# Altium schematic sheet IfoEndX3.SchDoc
size C; Engineer: Daniel Sigg; DocumentNumber: 7; SheetNumber: 26; SheetTotal: 33
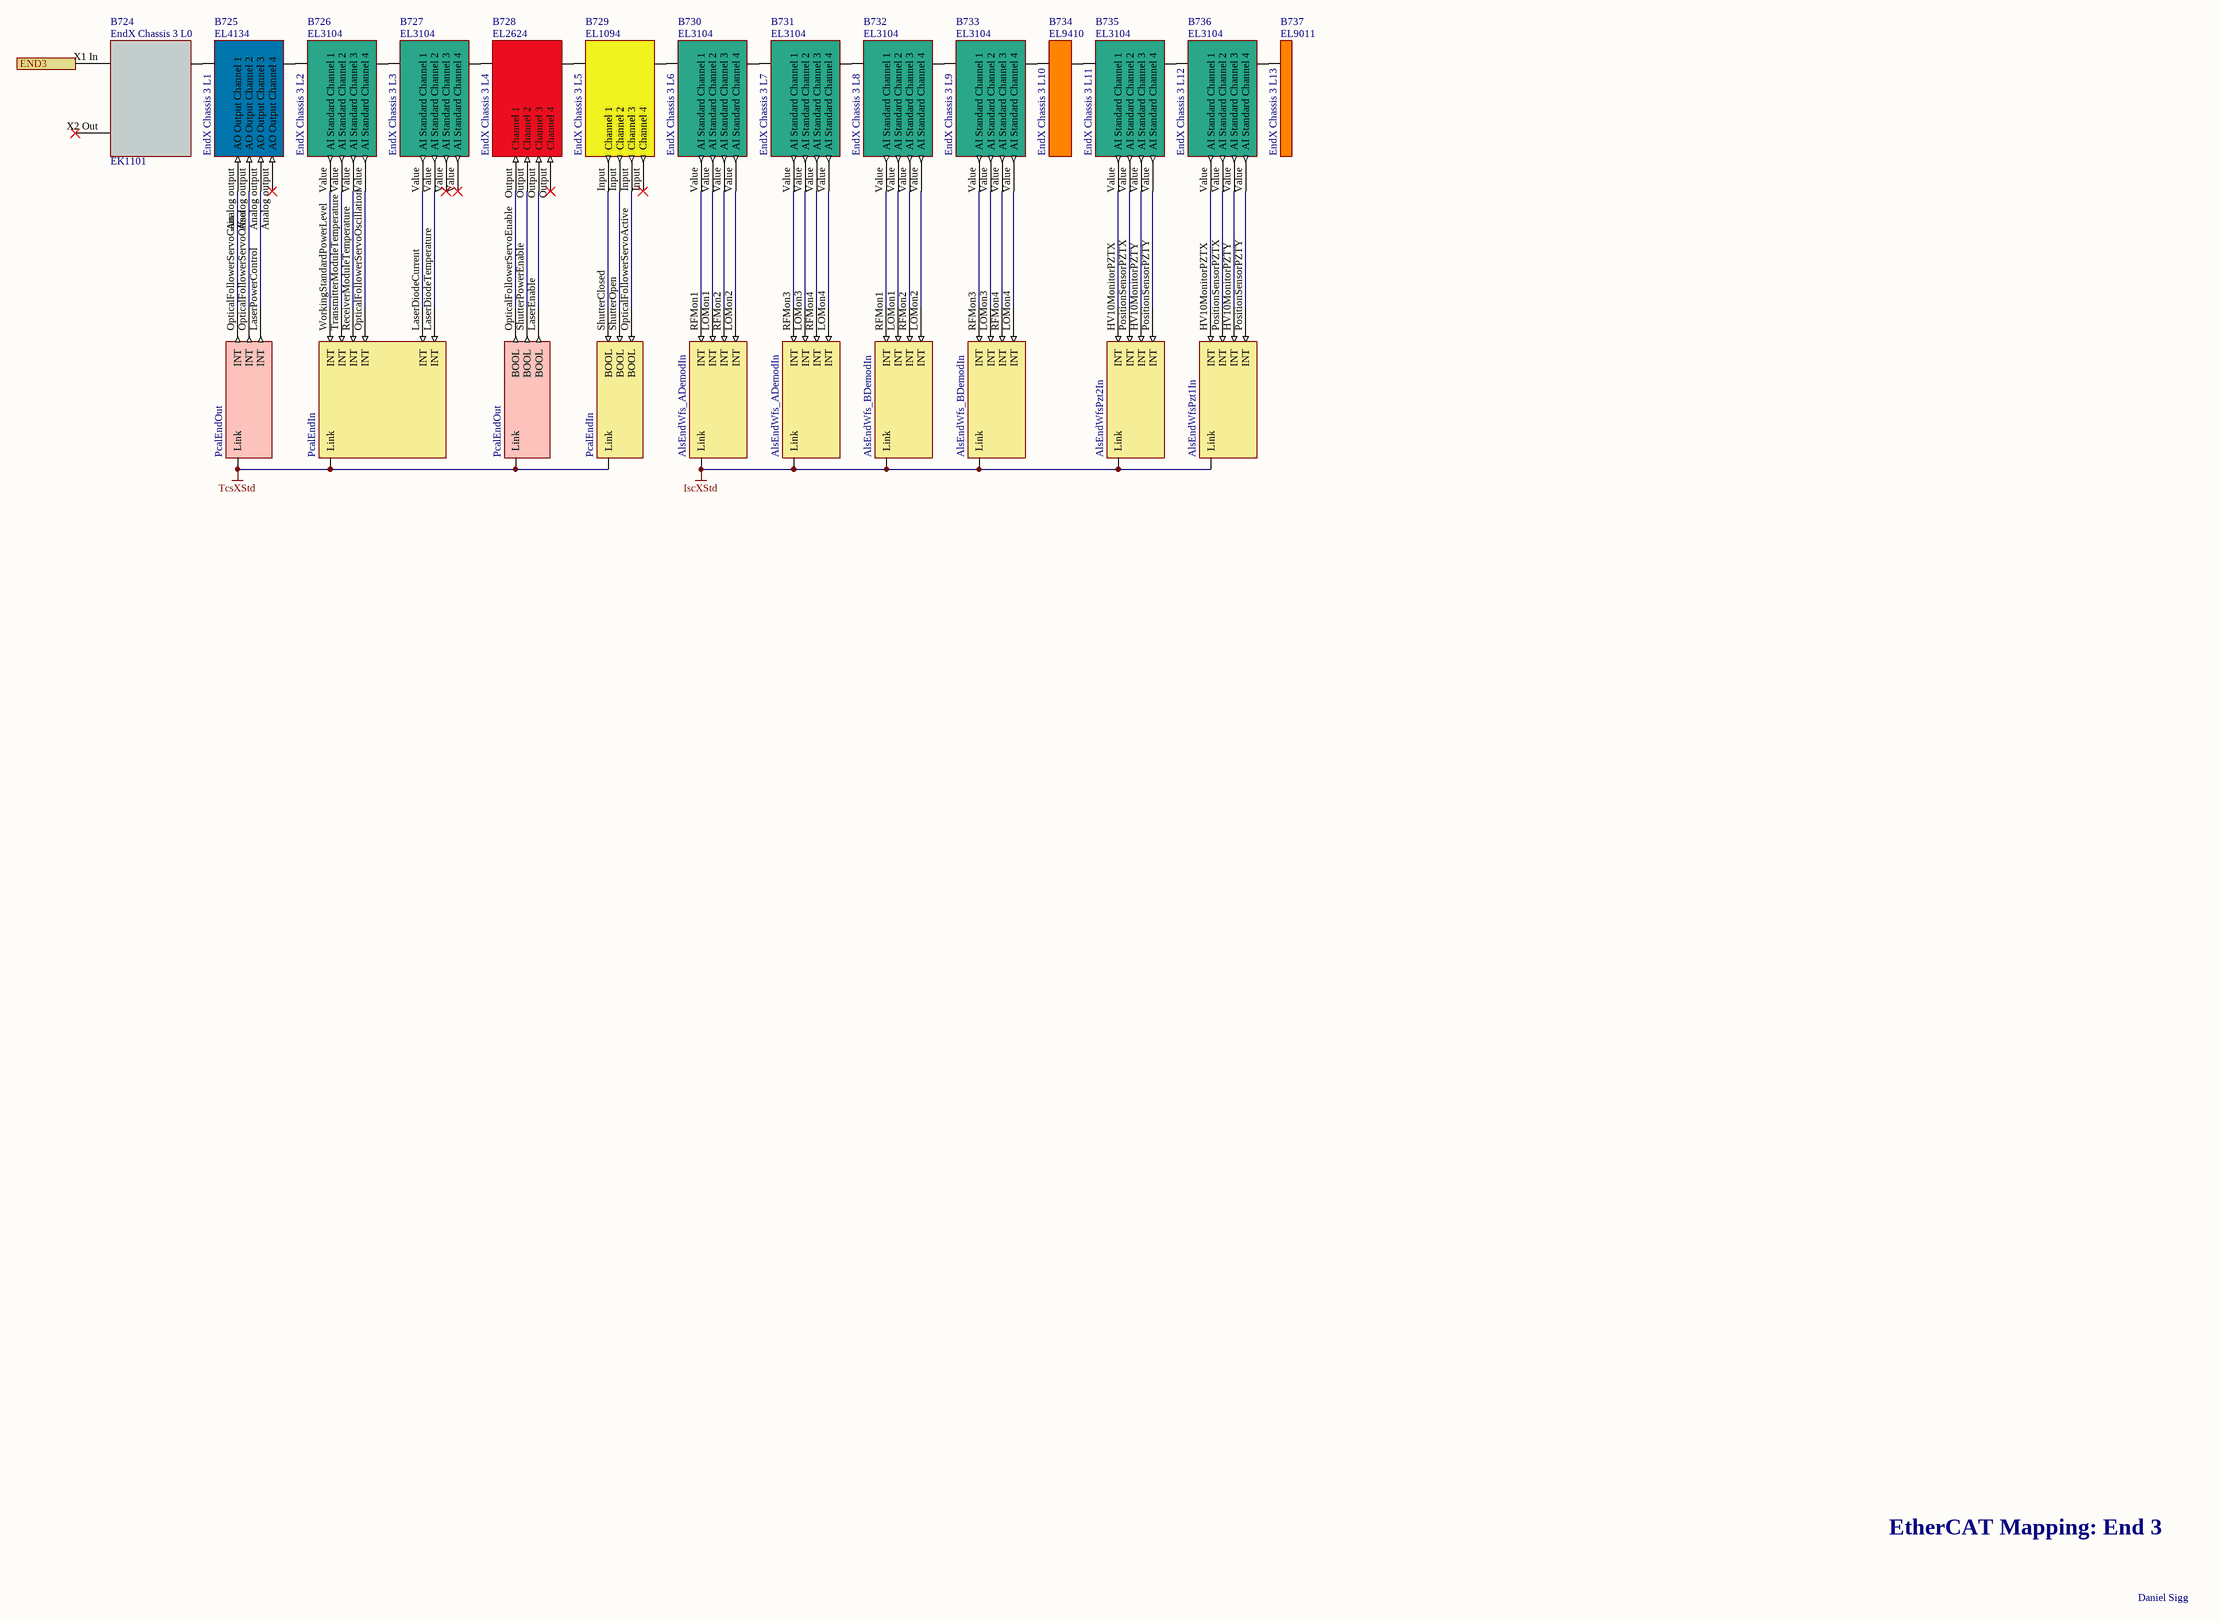
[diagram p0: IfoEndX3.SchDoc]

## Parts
B724  EndX Chassis 3 L0  Part Number: EK1101
B725  EndX Chassis 3 L1  Part Number: EL4134  (mechanical)
B726  EndX Chassis 3 L2  Part Number: EL3104  (mechanical)
B727  EndX Chassis 3 L3  Part Number: EL3104  (mechanical)
B728  EndX Chassis 3 L4  Part Number: EL2624  (mechanical)
B729  EndX Chassis 3 L5  Part Number: EL1094  (mechanical)
B730  EndX Chassis 3 L6  Part Number: EL3104  (mechanical)
B731  EndX Chassis 3 L7  Part Number: EL3104  (mechanical)
B732  EndX Chassis 3 L8  Part Number: EL3104  (mechanical)
B733  EndX Chassis 3 L9  Part Number: EL3104  (mechanical)
B734  EndX Chassis 3 L10  Part Number: EL9410  (mechanical)
B735  EndX Chassis 3 L11  Part Number: EL3104  (mechanical)
B736  EndX Chassis 3 L12  Part Number: EL3104  (mechanical)
B737  EndX Chassis 3 L13  Part Number: EL9011  (mechanical)
V584  PcalEndOut  (parts A,B of 2)  (no BOM)
V585  PcalEndIn  (parts A,B of 2)  (no BOM)
V586  AlsEndWfs_ADemodIn  (parts A,B of 2)  (no BOM)
V594  AlsEndWfs_BDemodIn  (parts A,B of 2)  (no BOM)
V595  AlsEndWfsPzt2In  (no BOM)
V596  AlsEndWfsPzt1In  (no BOM)

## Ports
END3

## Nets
IscXStd: V586.0(Link) V586.1(Link) V594.0(Link) V594.1(Link) V595.0(Link) V596.0(Link)
TcsXStd: V584.0(Link) V584.1(Link) V585.0(Link) V585.1(Link)
END3: B724.X1_In(A) ; port END3
NetB724_Ebus: B724.Ebus(B) B725.Ebus(A)
NetB725_Analog output: B725.Analog_output(AO_Output_Channel_1) V584.OpticalFollowerServoGain(INT)
NetB725_Analog output: B725.Analog_output(AO_Output_Channel_2) V584.OpticalFollowerServoOffset(INT)  [a separate net that carries the same name]
NetB725_Analog output: B725.Analog_output(AO_Output_Channel_3) V584.LaserPowerControl(INT)  [a separate net that carries the same name]
NetB725_Ebus: B725.Ebus(B) B726.Ebus(A)
NetB726_Ebus: B726.Ebus(B) B727.Ebus(A)
NetB726_Value: B726.Value(AI_Standard_Channel_1) V585.WorkingStandardPowerLevel(INT)
NetB726_Value: B726.Value(AI_Standard_Channel_2) V585.TransmitterModuleTemperature(INT)  [a separate net that carries the same name]
NetB726_Value: B726.Value(AI_Standard_Channel_3) V585.ReceiverModuleTemperature(INT)  [a separate net that carries the same name]
NetB726_Value: B726.Value(AI_Standard_Channel_4) V585.OpticalFollowerServoOscillation(INT)  [a separate net that carries the same name]
NetB727_Ebus: B727.Ebus(B) B728.Ebus(A)
NetB727_Value: B727.Value(AI_Standard_Channel_1) V585.LaserDiodeCurrent(INT)
NetB727_Value: B727.Value(AI_Standard_Channel_2) V585.LaserDiodeTemperature(INT)  [a separate net that carries the same name]
NetB728_Ebus: B728.Ebus(B) B729.Ebus(A)
NetB728_Output: B728.Output(Channel_1) V584.OpticalFollowerServoEnable(BOOL)
NetB728_Output: B728.Output(Channel_2) V584.ShutterPowerEnable(BOOL)  [a separate net that carries the same name]
NetB728_Output: B728.Output(Channel_3) V584.LaserEnable(BOOL)  [a separate net that carries the same name]
NetB729_Ebus: B729.Ebus(B) B730.Ebus(A)
NetB729_Input: B729.Input(Channel_1) V585.ShutterClosed(BOOL)
NetB729_Input: B729.Input(Channel_2) V585.ShutterOpen(BOOL)  [a separate net that carries the same name]
NetB729_Input: B729.Input(Channel_3) V585.OpticalFollowerServoActive(BOOL)  [a separate net that carries the same name]
NetB730_Ebus: B730.Ebus(B) B731.Ebus(A)
NetB730_Value: B730.Value(AI_Standard_Channel_1) V586.RFMon1(INT)
NetB730_Value: B730.Value(AI_Standard_Channel_2) V586.LOMon1(INT)  [a separate net that carries the same name]
NetB730_Value: B730.Value(AI_Standard_Channel_3) V586.RFMon2(INT)  [a separate net that carries the same name]
NetB730_Value: B730.Value(AI_Standard_Channel_4) V586.LOMon2(INT)  [a separate net that carries the same name]
NetB731_Ebus: B731.Ebus(B) B732.Ebus(A)
NetB731_Value: B731.Value(AI_Standard_Channel_1) V586.RFMon3(INT)
NetB731_Value: B731.Value(AI_Standard_Channel_2) V586.LOMon3(INT)  [a separate net that carries the same name]
NetB731_Value: B731.Value(AI_Standard_Channel_3) V586.RFMon4(INT)  [a separate net that carries the same name]
NetB731_Value: B731.Value(AI_Standard_Channel_4) V586.LOMon4(INT)  [a separate net that carries the same name]
NetB732_Ebus: B732.Ebus(B) B733.Ebus(A)
NetB732_Value: B732.Value(AI_Standard_Channel_1) V594.RFMon1(INT)
NetB732_Value: B732.Value(AI_Standard_Channel_2) V594.LOMon1(INT)  [a separate net that carries the same name]
NetB732_Value: B732.Value(AI_Standard_Channel_3) V594.RFMon2(INT)  [a separate net that carries the same name]
NetB732_Value: B732.Value(AI_Standard_Channel_4) V594.LOMon2(INT)  [a separate net that carries the same name]
NetB733_Ebus: B733.Ebus(B) B734.Ebus(A)
NetB733_Value: B733.Value(AI_Standard_Channel_1) V594.RFMon3(INT)
NetB733_Value: B733.Value(AI_Standard_Channel_2) V594.LOMon3(INT)  [a separate net that carries the same name]
NetB733_Value: B733.Value(AI_Standard_Channel_3) V594.RFMon4(INT)  [a separate net that carries the same name]
NetB733_Value: B733.Value(AI_Standard_Channel_4) V594.LOMon4(INT)  [a separate net that carries the same name]
NetB734_Ebus: B734.Ebus(B) B735.Ebus(A)
NetB735_Ebus: B735.Ebus(B) B736.Ebus(A)
NetB735_Value: B735.Value(AI_Standard_Channel_1) V595.HV10MonitorPZTX(INT)
NetB735_Value: B735.Value(AI_Standard_Channel_2) V595.PositionSensorPZTX(INT)  [a separate net that carries the same name]
NetB735_Value: B735.Value(AI_Standard_Channel_3) V595.HV10MonitorPZTY(INT)  [a separate net that carries the same name]
NetB735_Value: B735.Value(AI_Standard_Channel_4) V595.PositionSensorPZTY(INT)  [a separate net that carries the same name]
NetB736_Ebus: B736.Ebus(B) B737.Ebus(A)
NetB736_Value: B736.Value(AI_Standard_Channel_1) V596.HV10MonitorPZTX(INT)
NetB736_Value: B736.Value(AI_Standard_Channel_2) V596.PositionSensorPZTX(INT)  [a separate net that carries the same name]
NetB736_Value: B736.Value(AI_Standard_Channel_3) V596.HV10MonitorPZTY(INT)  [a separate net that carries the same name]
NetB736_Value: B736.Value(AI_Standard_Channel_4) V596.PositionSensorPZTY(INT)  [a separate net that carries the same name]

Not connected (* = marked no-connect by the designer): B724 X2 Out(C)*

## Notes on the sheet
- EtherCAT Mapping: End 3
- Daniel Sigg

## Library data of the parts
B724 = CouplerEK1101: EtherCAT Coupler; Rail: Left; BoxNextB: JOALOQYJ; BoxPrev: WVQJRASG; PortPrevFull: 1088/C; PortPrevShort: C 'X2 Out'; Fullname: TIID^End X (EtherCAT)^EndX Link L0 (EK1501-0010)^EndX Link L6 (EK1521)^EndX Chassis 3 L0 (EK1101); BoxPorts: Junction; BoxAddr: 1101; Disabled: False
B725 = TerminalEL4134: EtherCAT Terminal EL4134 4-chn Analog Ouput; Rail: Left; BoxNextB: TMDQTKXU; BoxPrev: SGKBFUAI; PortPrevFull: 1101/B; PortPrevShort: B; Fullname: TIID^End X (EtherCAT)^EndX Link L0 (EK1501-0010)^EndX Link L6 (EK1521)^EndX Chassis 3 L0 (EK1101)^EndX Chassis 3 L1 (EL4134); BoxAddr: 1102; Disabled: False
B726 = TerminalEL3104: EtherCAT Terminal EL3104 4-chn Analog Input; Rail: Left; BoxNextB: WWLRMYVT; BoxPrev: JOALOQYJ; PortPrevFull: 1102/B; PortPrevShort: B; Fullname: TIID^End X (EtherCAT)^EndX Link L0 (EK1501-0010)^EndX Link L6 (EK1521)^EndX Chassis 3 L0 (EK1101)^EndX Chassis 3 L2 (EL3104); BoxAddr: 1103; Disabled: False
B727 = TerminalEL3104: EtherCAT Terminal EL3104 4-chn Analog Input; Rail: Left; BoxNextB: ASHOYETR; BoxPrev: TMDQTKXU; PortPrevFull: 1103/B; PortPrevShort: B; Fullname: TIID^End X (EtherCAT)^EndX Link L0 (EK1501-0010)^EndX Link L6 (EK1521)^EndX Chassis 3 L0 (EK1101)^EndX Chassis 3 L3 (EL3104); BoxAddr: 1104; Disabled: False
B728 = TerminalEL2624: EtherCAT Terminal EL2624 4-channel relay output terminal 125 V AC/30 V DC; Rail: Left; BoxNextB: DBIHPMGF; BoxPrev: WWLRMYVT; PortPrevFull: 1104/B; PortPrevShort: B; Fullname: TIID^End X (EtherCAT)^EndX Link L0 (EK1501-0010)^EndX Link L6 (EK1521)^EndX Chassis 3 L0 (EK1101)^EndX Chassis 3 L4 (EL2624); BoxAddr: 1105; Disabled: False
B729 = TerminalEL1094: EtherCAT Terminal EL1094 4-channel digital input terminal 24 V DC, switching to negative potential; Rail: Left; BoxNextB: LUIRLPUG; BoxPrev: ASHOYETR; PortPrevFull: 1105/B; PortPrevShort: B; Fullname: TIID^End X (EtherCAT)^EndX Link L0 (EK1501-0010)^EndX Link L6 (EK1521)^EndX Chassis 3 L0 (EK1101)^EndX Chassis 3 L5 (EL1094); BoxAddr: 1106; Disabled: False
B730 = TerminalEL3104: EtherCAT Terminal EL3104 4-chn Analog Input; Rail: Left; BoxNextB: KBUQGUSU; BoxPrev: DBIHPMGF; PortPrevFull: 1106/B; PortPrevShort: B; Fullname: TIID^End X (EtherCAT)^EndX Link L0 (EK1501-0010)^EndX Link L6 (EK1521)^EndX Chassis 3 L0 (EK1101)^EndX Chassis 3 L6 (EL3104); BoxAddr: 1107; Disabled: False
B731 = TerminalEL3104: EtherCAT Terminal EL3104 4-chn Analog Input; Rail: Left; BoxNextB: TITKQTNS; BoxPrev: LUIRLPUG; PortPrevFull: 1107/B; PortPrevShort: B; Fullname: TIID^End X (EtherCAT)^EndX Link L0 (EK1501-0010)^EndX Link L6 (EK1521)^EndX Chassis 3 L0 (EK1101)^EndX Chassis 3 L7 (EL3104); BoxAddr: 1108; Disabled: False
B732 = TerminalEL3104: EtherCAT Terminal EL3104 4-chn Analog Input; Rail: Left; BoxNextB: LHUKNTVD; BoxPrev: KBUQGUSU; PortPrevFull: 1108/B; PortPrevShort: B; Fullname: TIID^End X (EtherCAT)^EndX Link L0 (EK1501-0010)^EndX Link L6 (EK1521)^EndX Chassis 3 L0 (EK1101)^EndX Chassis 3 L8 (EL3104); BoxAddr: 1109; Disabled: False
B733 = TerminalEL3104: EtherCAT Terminal EL3104 4-chn Analog Input; Rail: Left; BoxNextB: EPCNRMUG; BoxPrev: TITKQTNS; PortPrevFull: 1109/B; PortPrevShort: B; Fullname: TIID^End X (EtherCAT)^EndX Link L0 (EK1501-0010)^EndX Link L6 (EK1521)^EndX Chassis 3 L0 (EK1101)^EndX Chassis 3 L9 (EL3104); BoxAddr: 1110; Disabled: False
B734 = TerminalEL9410: EtherCAT Terminal EL9410 Power; Rail: Left; BoxNextB: BWFIVQXF; BoxPrev: LHUKNTVD; PortPrevFull: 1110/B; PortPrevShort: B; Fullname: TIID^End X (EtherCAT)^EndX Link L0 (EK1501-0010)^EndX Link L6 (EK1521)^EndX Chassis 3 L0 (EK1101)^EndX Chassis 3 L10 (EL9410); BoxAddr: 1111; Disabled: False
B735 = TerminalEL3104: EtherCAT Terminal EL3104 4-chn Analog Input; Rail: Left; BoxNextB: YQQYJIVR; BoxPrev: EPCNRMUG; PortPrevFull: 1111/B; PortPrevShort: B; Fullname: TIID^End X (EtherCAT)^EndX Link L0 (EK1501-0010)^EndX Link L6 (EK1521)^EndX Chassis 3 L0 (EK1101)^EndX Chassis 3 L11 (EL3104); BoxAddr: 1112; Disabled: False
B736 = TerminalEL3104: EtherCAT Terminal EL3104 4-chn Analog Input; Rail: Left; BoxNextB: TREKMSTE; BoxPrev: BWFIVQXF; PortPrevFull: 1112/B; PortPrevShort: B; Fullname: TIID^End X (EtherCAT)^EndX Link L0 (EK1501-0010)^EndX Link L6 (EK1521)^EndX Chassis 3 L0 (EK1101)^EndX Chassis 3 L12 (EL3104); BoxAddr: 1113; Disabled: False
B737 = TerminalEL9011: EtherCAT Terminal EL9011 End; BoxType: TerminalPassive; Rail: Left; BoxPrev: YQQYJIVR; PortPrevShort: B; Fullname: TIID^End X (EtherCAT)^EndX Link L0 (EK1501-0010)^EndX Link L6 (EK1521)^EndX Chassis 3 L0 (EK1101)^EndX Chassis 3 L13 (EL9011); Disabled: False
V584 = Pcal_PcalOutStruct: PcalOutStruct; BoxType: Variable; Instance: H1TcsEndX Instance; PLC: H1TcsEndX; Task: TcsEStd
V585 = Pcal_PcalInStruct: PcalInStruct; BoxType: Variable; Instance: H1TcsEndX Instance; PLC: H1TcsEndX; Task: TcsEStd
V586 V594 = Demodulator_DemodulatorQuadInStruct: DemodulatorQuadInStruct; BoxType: Variable; Instance: H1IscEndX Instance; PLC: H1IscEndX; Task: IscEStd
V595 V596 = PZTMirror_PZTMirrorInStruct: PZTMirrorInStruct; BoxType: Variable; Instance: H1IscEndX Instance; PLC: H1IscEndX; Task: IscEStd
